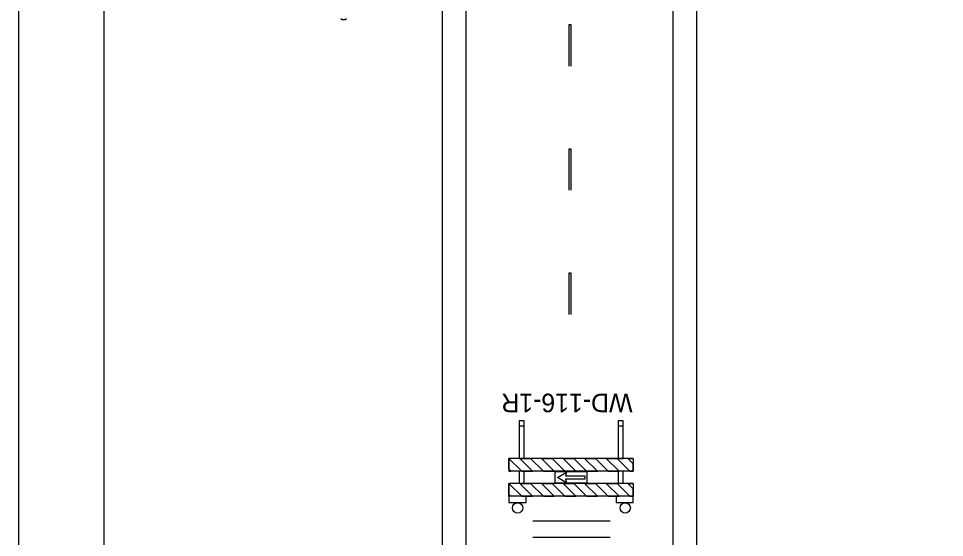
# Model space of a CAD drawing. Extents: x 797 to 1013, y 120 to 399.
# Drawn here: x 797.2 to 905.6, y 270.1 to 330.8 of the extents above; entities that cross this region are included whole.
import ezdxf

# ---------------------------------------------------------------- set-up
doc = ezdxf.new("R2010")
doc.units = 0
for name, color, linetype in [('Level 10', 7, 'Continuous'), ('Level 2', 7, 'Continuous'), ('Level 44', 7, 'Continuous'), ('Level 5', 7, 'Continuous'), ('Level 60', 7, 'Continuous')]:
    doc.layers.add(name, color=color, linetype=linetype)

msp = doc.modelspace()

# ---------------------------------------------------------------- linework, layer by layer
at = {"layer": 'Level 10'}
for p, q in [((846.78, 383.98), (846.78, 135.76)), ((849.54, 383.98), (849.54, 135.76)), ((873.78, 383.98), (873.78, 135.76)), ((876.53, 383.98), (876.53, 135.76)), ((860.01, 276.42), (860.01, 277.79)), ((860.01, 277.79), (863.69, 277.79)), ((860.25, 277.11), (861.33, 277.72)), ((861.33, 277.72), (861.21, 277.3)), ((863.69, 277.79), (863.69, 276.42)), ((861.33, 276.49), (860.25, 277.11)), ((861.21, 277.3), (863.45, 277.3)), ((863.45, 276.91), (861.21, 276.91)), ((861.21, 276.91), (861.33, 276.49)), ((863.45, 277.3), (863.45, 276.91)), ((863.69, 276.42), (860.01, 276.42)), ((857.39, 272.03), (866.43, 272.03)), ((857.39, 270.1), (866.43, 270.1))]:
    msp.add_line(p, q, dxfattribs=at)
for points in [[(856.59, 274.91), (854.58, 274.91), (854.58, 274.18), (856.59, 274.18)], [(869.14, 274.91), (867.14, 274.91), (867.14, 274.18), (869.14, 274.18)]]:
    msp.add_lwpolyline(points, close=True, dxfattribs=at)
for centre in [(855.6, 273.54), (868.19, 273.54)]:
    msp.add_circle(centre, 0.606, dxfattribs=at)
at = {"layer": 'Level 2'}
for p, q in [((861.59, 330.05), (861.59, 325.21)), ((861.88, 330.05), (861.59, 330.05)), ((861.88, 325.21), (861.88, 330.05)), ((861.59, 315.53), (861.59, 310.7)), ((861.88, 315.53), (861.59, 315.53)), ((861.88, 310.7), (861.88, 315.53)), ((861.59, 301.02), (861.59, 296.18)), ((861.88, 301.02), (861.59, 301.02)), ((861.88, 296.18), (861.88, 301.02))]:
    msp.add_line(p, q, dxfattribs=at)
at = {"layer": 'Level 44'}
msp.add_arc((835.24, 331.13), 0.459, 225, 315, dxfattribs=at)
at = {"layer": 'Level 5'}
for p, q in [((856.37, 283.12), (855.77, 283.12)), ((867.95, 283.12), (867.35, 283.12)), ((869.14, 279.31), (854.58, 279.31)), ((854.58, 279.31), (854.58, 277.82)), ((869.14, 279.31), (869.14, 277.82)), ((869.14, 277.82), (854.58, 277.82)), ((863.69, 277.79), (860.01, 277.79)), ((863.69, 277.79), (860.01, 277.79)), ((867.95, 277.82), (867.65, 277.82)), ((863.45, 276.91), (861.21, 276.91)), ((861.21, 276.91), (861.33, 276.49)), ((863.45, 277.3), (863.45, 276.91)), ((854.58, 276.4), (854.58, 274.91)), ((869.14, 276.4), (854.58, 276.4)), ((855.77, 276.43), (855.77, 276.4)), ((860.01, 276.42), (863.69, 276.42)), ((860.01, 276.42), (863.69, 276.42)), ((867.35, 276.43), (867.35, 276.4)), ((869.14, 276.4), (869.14, 274.91)), ((869.14, 274.91), (854.58, 274.91)), ((867.95, 274.91), (867.65, 274.91))]:
    msp.add_line(p, q, dxfattribs=at)
for points in [[(855.77, 279.33), (856.37, 279.33), (856.37, 283.71), (855.77, 283.71)], [(867.35, 279.33), (867.95, 279.33), (867.95, 283.71), (867.35, 283.71)], [(856.07, 277.82), (857.34, 277.82), (855.85, 279.31), (854.58, 279.31)], [(858.61, 277.82), (859.87, 277.82), (858.38, 279.31), (857.11, 279.31)], [(861.14, 277.82), (862.4, 277.82), (860.91, 279.31), (859.64, 279.31)], [(863.67, 277.82), (864.94, 277.82), (863.44, 279.31), (862.18, 279.31)], [(866.2, 277.82), (867.47, 277.82), (865.98, 279.31), (864.71, 279.31)], [(868.73, 277.82), (869.14, 277.82), (869.14, 278.68), (868.51, 279.31), (867.24, 279.31)], [(854.58, 277.82), (854.81, 277.82), (854.58, 278.05)], [(855.77, 276.43), (856.37, 276.4), (856.37, 277.82), (855.77, 277.82)], [(867.35, 276.43), (867.95, 276.43), (867.95, 277.82), (867.35, 277.82)], [(856.07, 274.91), (857.34, 274.91), (855.85, 276.4), (854.58, 276.4)], [(858.61, 274.91), (859.87, 274.91), (858.38, 276.4), (857.11, 276.4)], [(861.14, 274.91), (862.4, 274.91), (860.91, 276.4), (859.64, 276.4)], [(863.67, 274.91), (864.94, 274.91), (863.44, 276.4), (862.18, 276.4)], [(866.2, 274.91), (867.47, 274.91), (865.98, 276.4), (864.71, 276.4)], [(868.73, 274.91), (869.14, 274.91), (869.14, 275.77), (868.51, 276.4), (867.24, 276.4)], [(854.81, 274.91), (854.58, 274.91), (854.58, 275.14)]]:
    msp.add_lwpolyline(points, close=True, dxfattribs=at)
for points in [[(854.58, 279.31), (856.07, 277.82), (854.81, 277.82), (854.58, 278.05), (854.58, 279.31)], [(857.11, 279.31), (858.61, 277.82), (857.34, 277.82), (855.85, 279.31), (857.11, 279.31)], [(859.64, 279.31), (861.14, 277.82), (859.87, 277.82), (858.38, 279.31), (859.64, 279.31)], [(862.18, 279.31), (863.67, 277.82), (862.4, 277.82), (860.91, 279.31), (862.18, 279.31)], [(866.2, 277.82), (864.94, 277.82), (863.44, 279.31), (864.71, 279.31), (866.2, 277.82)], [(868.73, 277.82), (867.47, 277.82), (865.98, 279.31), (867.24, 279.31), (868.73, 277.82)], [(869.14, 278.68), (868.51, 279.31), (869.14, 279.31), (869.14, 278.68)], [(854.58, 276.4), (856.07, 274.91), (854.81, 274.91), (854.58, 275.14), (854.58, 276.4)], [(857.11, 276.4), (858.61, 274.91), (857.34, 274.91), (855.85, 276.4), (857.11, 276.4)], [(859.64, 276.4), (861.14, 274.91), (859.87, 274.91), (858.38, 276.4), (859.64, 276.4)], [(862.18, 276.4), (863.67, 274.91), (862.4, 274.91), (860.91, 276.4), (862.18, 276.4)], [(866.2, 274.91), (864.94, 274.91), (863.44, 276.4), (864.71, 276.4), (866.2, 274.91)], [(868.73, 274.91), (867.47, 274.91), (865.98, 276.4), (867.24, 276.4), (868.73, 274.91)], [(869.14, 275.77), (868.51, 276.4), (869.14, 276.4), (869.14, 275.77)]]:
    msp.add_lwpolyline(points, dxfattribs=at)
at = {"layer": 'Level 60'}
for points in [[(1013.16, 399.38), (797.16, 399.38), (797.16, 120.38), (1013.16, 120.38)], [(994.03, 388.57), (807.16, 388.57), (807.16, 131.19), (994.03, 131.19)]]:
    msp.add_lwpolyline(points, close=True, dxfattribs=at)

# ---------------------------------------------------------------- texts
at = {"layer": 'Level 10'}
msp.add_text('WD-116-1R', height=2.177, rotation=180, dxfattribs=at).set_placement((869.05, 286.91))

doc.saveas('drawing.dxf')
